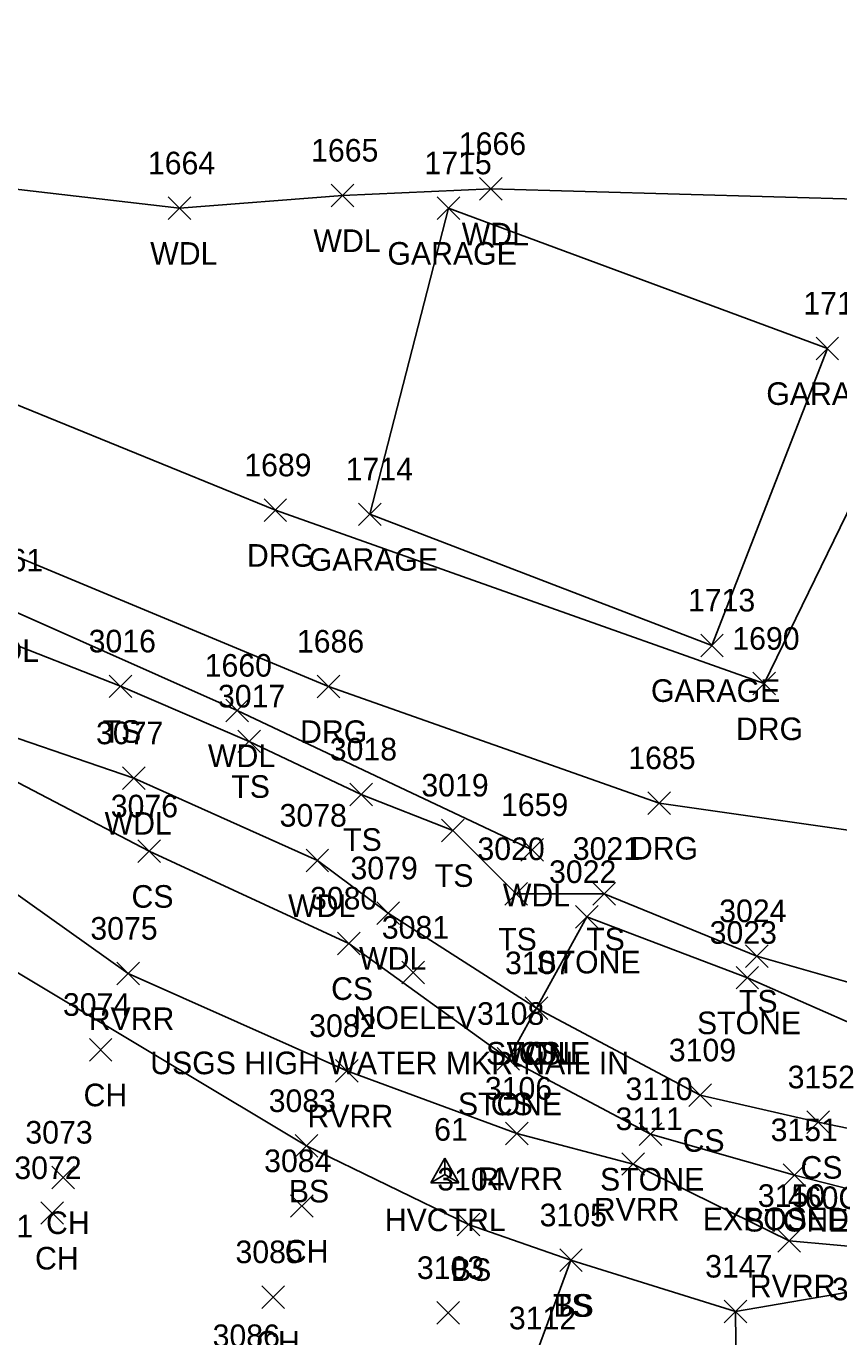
# Model space of a CAD drawing. Extents: x 462930 to 463548, y 29607 to 30453.
# Drawn here: x 463320.55 to 463342.46, y 30140.5 to 30175.85 of the extents above; entities that cross this region are included whole.
import ezdxf

# ---------------------------------------------------------------- set-up
doc = ezdxf.new("R2010")
doc.units = 0
for name, color, linetype in [('C_A', 7, 'Continuous'), ('C_I', 7, 'Continuous'), ('CPSM', 7, 'Continuous'), ('D_C', 7, 'Continuous'), ('L_A', 7, 'Continuous'), ('L_I', 7, 'Continuous'), ('L_TIC', 7, 'Continuous'), ('LASF', 7, 'Continuous'), ('LAWA', 7, 'Continuous'), ('LAWE', 7, 'Continuous'), ('LBC', 7, 'Continuous'), ('LELB', 7, 'Continuous'), ('M_A', 7, 'Continuous'), ('M_C', 7, 'Continuous'), ('M_I', 7, 'Continuous'), ('M_TIC', 7, 'Continuous'), ('R_A', 7, 'Continuous'), ('R_I', 7, 'Continuous'), ('R_TIC', 7, 'Continuous'), ('RDG', 7, 'Continuous'), ('U_C', 7, 'Continuous')]:
    doc.layers.add(name, color=color, linetype=linetype)

msp = doc.modelspace()

# ---------------------------------------------------------------- linework, layer by layer
at = {"layer": 'CPSM'}
for p, q in [((463331.458, 30144.654), (463331.839, 30145.314)), ((463332.22, 30144.654), (463331.839, 30145.314)), ((463331.839, 30144.874), (463331.839, 30145.314)), ((463331.458, 30144.654), (463331.839, 30144.874)), ((463331.458, 30144.654), (463332.22, 30144.654)), ((463331.839, 30144.874), (463331.839, 30144.874)), ((463331.839, 30144.874), (463332.22, 30144.654))]:
    msp.add_line(p, q, dxfattribs=at)
at = {"layer": 'L_TIC'}
for points in [[(463328.779, 30170.977), (463329.389, 30171.587)], [(463329.389, 30170.977), (463328.779, 30171.587)], [(463332.778, 30171.156), (463333.388, 30171.766)], [(463333.388, 30171.156), (463332.778, 30171.766)], [(463324.379, 30170.634), (463324.989, 30171.244)], [(463324.989, 30170.634), (463324.379, 30171.244)], [(463331.633, 30170.635), (463332.243, 30171.245)], [(463332.243, 30170.635), (463331.633, 30171.245)], [(463341.846, 30166.853), (463342.456, 30167.463)], [(463342.456, 30166.853), (463341.846, 30167.463)], [(463329.51, 30162.378), (463330.12, 30162.988)], [(463330.12, 30162.378), (463329.51, 30162.988)], [(463338.736, 30158.843), (463339.346, 30159.453)], [(463339.346, 30158.843), (463338.736, 30159.453)], [(463322.793, 30157.74), (463323.403, 30158.349)], [(463323.403, 30157.74), (463322.793, 30158.349)], [(463325.936, 30157.086), (463326.546, 30157.696)], [(463326.546, 30157.086), (463325.936, 30157.696)], [(463326.263, 30156.255), (463326.872, 30156.865)], [(463326.872, 30156.255), (463326.263, 30156.865)], [(463323.15, 30155.262), (463323.76, 30155.872)], [(463323.76, 30155.262), (463323.15, 30155.872)], [(463329.277, 30154.825), (463329.887, 30155.435)], [(463329.887, 30154.825), (463329.277, 30155.435)], [(463331.749, 30153.854), (463332.359, 30154.464)], [(463332.359, 30153.854), (463331.749, 30154.464)], [(463323.563, 30153.291), (463324.172, 30153.901)], [(463324.172, 30153.291), (463323.563, 30153.901)], [(463333.886, 30153.327), (463334.496, 30153.937)], [(463334.496, 30153.327), (463333.886, 30153.937)], [(463328.097, 30153.041), (463328.706, 30153.65)], [(463328.706, 30153.041), (463328.097, 30153.65)], [(463333.457, 30152.139), (463334.066, 30152.749)], [(463334.066, 30152.139), (463333.457, 30152.749)], [(463335.829, 30152.142), (463336.438, 30152.752)], [(463336.438, 30152.142), (463335.829, 30152.752)], [(463330.01, 30151.619), (463330.62, 30152.228)], [(463330.62, 30151.619), (463330.01, 30152.228)], [(463335.361, 30151.52), (463335.971, 30152.129)], [(463335.971, 30151.52), (463335.361, 30152.129)], [(463335.361, 30151.52), (463335.971, 30152.129)], [(463335.971, 30151.52), (463335.361, 30152.129)], [(463328.944, 30150.805), (463329.554, 30151.414)], [(463329.554, 30150.805), (463328.944, 30151.414)], [(463339.948, 30150.464), (463340.558, 30151.074)], [(463340.558, 30150.464), (463339.948, 30151.074)], [(463322.996, 30149.992), (463323.606, 30150.601)], [(463323.606, 30149.992), (463322.996, 30150.601)], [(463339.689, 30149.881), (463340.299, 30150.491)], [(463340.299, 30149.881), (463339.689, 30150.491)], [(463334.002, 30149.061), (463334.612, 30149.67)], [(463334.612, 30149.061), (463334.002, 30149.67)], [(463334.002, 30149.061), (463334.612, 30149.67)], [(463334.612, 30149.061), (463334.002, 30149.67)], [(463334.002, 30149.061), (463334.612, 30149.67)], [(463334.612, 30149.061), (463334.002, 30149.67)], [(463322.256, 30147.938), (463322.866, 30148.547)], [(463322.866, 30147.938), (463322.256, 30148.547)], [(463333.246, 30147.695), (463333.856, 30148.305)], [(463333.856, 30147.695), (463333.246, 30148.305)], [(463333.246, 30147.695), (463333.856, 30148.305)], [(463333.856, 30147.695), (463333.246, 30148.305)], [(463328.895, 30147.368), (463329.505, 30147.977)], [(463329.505, 30147.368), (463328.895, 30147.977)], [(463338.42, 30146.71), (463339.029, 30147.319)], [(463339.029, 30146.71), (463338.42, 30147.319)], [(463338.42, 30146.71), (463339.029, 30147.319)], [(463339.029, 30146.71), (463338.42, 30147.319)], [(463341.597, 30145.983), (463342.207, 30146.593)], [(463342.207, 30145.983), (463341.597, 30146.593)], [(463333.476, 30145.678), (463334.086, 30146.287)], [(463334.086, 30145.678), (463333.476, 30146.287)], [(463337.077, 30145.664), (463337.687, 30146.273)], [(463337.687, 30145.664), (463337.077, 30146.273)], [(463327.803, 30145.343), (463328.413, 30145.952)], [(463328.413, 30145.343), (463327.803, 30145.952)], [(463336.612, 30144.856), (463337.222, 30145.465)], [(463337.222, 30144.856), (463336.612, 30145.465)], [(463321.244, 30144.492), (463321.854, 30145.101)], [(463321.854, 30144.492), (463321.244, 30145.101)], [(463340.964, 30144.558), (463341.574, 30145.168)], [(463341.574, 30144.558), (463340.964, 30145.168)], [(463327.681, 30143.723), (463328.291, 30144.333)], [(463328.291, 30143.723), (463327.681, 30144.333)], [(463320.947, 30143.535), (463321.557, 30144.144)], [(463321.557, 30143.535), (463320.947, 30144.144)], [(463332.176, 30143.227), (463332.785, 30143.837)], [(463332.785, 30143.227), (463332.176, 30143.837)], [(463340.819, 30142.784), (463341.429, 30143.394)], [(463341.429, 30142.784), (463340.819, 30143.394)], [(463334.935, 30142.261), (463335.545, 30142.87)], [(463335.545, 30142.261), (463334.935, 30142.87)], [(463334.935, 30142.261), (463335.545, 30142.87)], [(463335.545, 30142.261), (463334.935, 30142.87)], [(463326.908, 30141.267), (463327.518, 30141.876)], [(463327.518, 30141.267), (463326.908, 30141.876)], [(463331.625, 30140.84), (463332.235, 30141.449)], [(463332.235, 30140.84), (463331.625, 30141.449)], [(463339.373, 30140.878), (463339.983, 30141.488)], [(463339.983, 30140.878), (463339.373, 30141.488)], [(463339.373, 30140.878), (463339.983, 30141.488)], [(463339.983, 30140.878), (463339.373, 30141.488)]]:
    msp.add_lwpolyline(points, dxfattribs=at)
at = {"layer": 'LASF'}
for points in [[(463335.666, 30151.825), (463334.307, 30149.365), (463333.551, 30148), (463337.382, 30145.968), (463341.269, 30144.863), (463346.266, 30143.58), (463350.176, 30142.23), (463354.589, 30140.054), (463359.587, 30137.022), (463360.802, 30137.163)], [(463335.666, 30151.825), (463339.994, 30150.186), (463344.731, 30148.092), (463345.991, 30147.14), (463346.905, 30145.251), (463349.408, 30144.305), (463351.788, 30143.206), (463354.335, 30142.295), (463356.35, 30141.031), (463357.426, 30140.903), (463358.46, 30140.002), (463361.001, 30139.273), (463362.41, 30138.437), (463365.572, 30136.833), (463366.432, 30136.349), (463367.765, 30135.728), (463368.18, 30135.769), (463368.592, 30135.381), (463370.057, 30136.689), (463370.978, 30134.911), (463374.408, 30132.631)]]:
    msp.add_lwpolyline(points, dxfattribs=at)
at = {"layer": 'LAWA'}
for points in [[(463334.191, 30153.632), (463326.241, 30157.391), (463319.877, 30160.227), (463314.478, 30162.732), (463317.175, 30171.812), (463324.684, 30170.939), (463329.084, 30171.282), (463333.083, 30171.461), (463343.25, 30171.173), (463352.596, 30169.581), (463356.899, 30175.447), (463361.663, 30184.45), (463356.272, 30186.994), (463347.611, 30186.575), (463333.194, 30190.781), (463330.167, 30185.817), (463328.348, 30182.689), (463321.007, 30182.589)], [(463314.174, 30158.759), (463318.783, 30157.171), (463323.455, 30155.567), (463328.402, 30153.346), (463330.315, 30151.924), (463334.307, 30149.365)]]:
    msp.add_lwpolyline(points, dxfattribs=at)
at = {"layer": 'LAWE'}
msp.add_lwpolyline([(463312.771, 30156.48), (463317.927, 30154.119), (463323.301, 30150.297), (463329.2, 30147.672), (463333.781, 30145.982), (463336.917, 30145.16), (463341.124, 30143.089), (463345.902, 30142.661), (463349.953, 30140.952), (463354.589, 30140.054), (463360.802, 30137.163), (463361.685, 30137.202), (463364.938, 30136.029), (463367.213, 30134.485), (463367.529, 30133.847), (463370.878, 30131.969), (463372.536, 30131.581), (463374.072, 30131.794), (463376.13, 30130.821), (463379.432, 30129.045)], dxfattribs=at)
at = {"layer": 'LBC'}
for points in [[(463342.151, 30167.158), (463339.041, 30159.148), (463329.815, 30162.683), (463331.938, 30170.94)], [(463331.938, 30170.94), (463342.151, 30167.158)]]:
    msp.add_lwpolyline(points, dxfattribs=at)
at = {"layer": 'LELB'}
for points in [[(463315.632, 30161.314), (463319.611, 30159.411), (463323.098, 30158.045), (463326.567, 30156.56), (463329.582, 30155.13), (463332.054, 30154.159), (463333.762, 30152.444), (463336.134, 30152.447), (463340.253, 30150.769), (463345.161, 30149.365), (463346.778, 30148.746), (463346.708, 30147.71), (463349.033, 30147.393), (463350.898, 30147.395), (463351.713, 30147.754), (463353.797, 30146.756), (463354.253, 30145.629), (463355.291, 30145.255), (463356.709, 30145.503), (463357.92, 30145.112), (463358.601, 30144.516), (463359.186, 30143.714)], [(463313.769, 30158.17), (463318.774, 30156.259), (463323.868, 30153.596), (463329.249, 30151.11), (463333.551, 30148)], [(463311.51, 30154.564), (463317.305, 30152.12), (463328.108, 30145.648), (463332.48, 30143.532), (463335.24, 30142.565), (463339.678, 30141.183), (463343.544, 30141.846), (463345.752, 30141.37), (463349.534, 30139.719), (463354.026, 30138.661), (463359.587, 30137.022), (463361.306, 30136.712), (463364.334, 30135.56), (463366.649, 30133.733), (463367.281, 30133.213), (463370.369, 30131.577), (463372.89, 30130.394), (463376, 30129.47), (463379.084, 30127.97)], [(463334.307, 30149.365), (463338.725, 30147.014)], [(463338.725, 30147.014), (463341.902, 30146.288), (463346.905, 30145.251), (463349.39, 30146.891), (463350.92, 30147.048), (463352.297, 30147.355), (463353.139, 30145.924), (463354.358, 30144.307), (463355.85, 30144.681), (463357.539, 30144.184), (463357.985, 30144.223), (463357.945, 30143.102), (463357.652, 30141.391), (463358.461, 30140.69), (463361.001, 30139.273)], [(463335.24, 30142.565), (463334.214, 30139.787), (463334.684, 30135.891)], [(463338.428, 30135.653), (463339.702, 30138.688), (463339.678, 30141.183)]]:
    msp.add_lwpolyline(points, dxfattribs=at)
at = {"layer": 'M_TIC'}
for points in [[(463330.68, 30150.02), (463331.289, 30150.63)], [(463331.289, 30150.02), (463330.68, 30150.63)]]:
    msp.add_lwpolyline(points, dxfattribs=at)
at = {"layer": 'R_TIC'}
for points in [[(463326.965, 30162.489), (463327.575, 30163.099)], [(463327.575, 30162.489), (463326.965, 30163.099)], [(463340.146, 30157.812), (463340.756, 30158.422)], [(463340.756, 30157.812), (463340.146, 30158.422)], [(463328.398, 30157.735), (463329.008, 30158.345)], [(463329.008, 30157.735), (463328.398, 30158.345)], [(463337.315, 30154.591), (463337.925, 30155.201)], [(463337.925, 30154.591), (463337.315, 30155.201)]]:
    msp.add_lwpolyline(points, dxfattribs=at)
at = {"layer": 'RDG'}
msp.add_lwpolyline([(463347.931, 30153.415), (463337.62, 30154.896), (463328.703, 30158.04), (463317.438, 30162.728), (463318.8, 30166.246), (463327.27, 30162.794), (463340.451, 30158.117), (463344.729, 30166.901), (463353.138, 30164.992), (463357.576, 30167.469)], dxfattribs=at)

# ---------------------------------------------------------------- texts
at = {"layer": 'C_A'}
msp.add_text('HVCTRL', height=0.6096, dxfattribs=at).set_placement((463330.221, 30143.35))
at = {"layer": 'C_I'}
msp.add_text('61', height=0.6096, dxfattribs=at).set_placement((463331.551, 30145.789))
at = {"layer": 'D_C'}
msp.add_text('460CGMP', height=0.6096, dxfattribs=at).set_placement((463341.089, 30143.947))
at = {"layer": 'L_A'}
for s, p in [('WDL', (463332.296, 30169.937)), ('WDL', (463323.897, 30169.415)), ('WDL', (463328.297, 30169.758)), ('GARAGE', (463330.292, 30169.416)), ('GARAGE', (463340.505, 30165.634)), ('GARAGE', (463328.169, 30161.159)), ('WDL', (463319.09, 30158.703)), ('GARAGE', (463337.395, 30157.624)), ('TS', (463322.613, 30156.521)), ('WDL', (463325.454, 30155.867)), ('TS', (463326.083, 30155.036)), ('WDL', (463322.668, 30154.043)), ('TS', (463329.097, 30153.606)), ('TS', (463331.569, 30152.635)), ('WDL', (463333.404, 30152.108)), ('CS', (463323.392, 30152.072)), ('WDL', (463327.614, 30151.822)), ('TS', (463333.277, 30150.92)), ('TS', (463335.649, 30150.923)), ('WDL', (463329.528, 30150.4)), ('STONE', (463334.308, 30150.301)), ('STONE', (463334.308, 30150.301)), ('CS', (463328.774, 30149.586)), ('TS', (463339.768, 30149.245)), ('RVRR', (463322.238, 30148.773)), ('STONE', (463338.636, 30148.662)), ('STONE', (463332.949, 30147.841)), ('CS', (463333.832, 30147.841)), ('WDL', (463333.52, 30147.841)), ('CH', (463322.1, 30146.718)), ('STONE', (463332.193, 30146.476)), ('CS', (463333.076, 30146.476)), ('RVRR', (463328.137, 30146.148)), ('CS', (463338.249, 30145.49)), ('CS', (463338.249, 30145.49)), ('CS', (463341.427, 30144.764)), ('RVRR', (463332.718, 30144.458)), ('STONE', (463336.024, 30144.444)), ('BS', (463327.633, 30144.124)), ('RVRR', (463335.854, 30143.636)), ('CH', (463321.088, 30143.272)), ('STONE', (463339.91, 30143.339)), ('CH', (463320.791, 30142.315)), ('CH', (463327.525, 30142.504)), ('BS', (463332.005, 30142.008)), ('RVRR', (463340.061, 30141.565)), ('TS', (463334.755, 30141.041)), ('BS', (463334.765, 30141.041)), ('CH', (463326.752, 30140.047))]:
    msp.add_text(s, height=0.6096, dxfattribs=at).set_placement(p)
at = {"layer": 'L_I'}
for s, p in [('1666', (463332.217, 30172.375)), ('1665', (463328.234, 30172.196)), ('1664', (463323.834, 30171.853)), ('1715', (463331.29, 30171.854)), ('1712', (463341.503, 30168.072)), ('1714', (463329.167, 30163.597)), ('1661', (463319.2, 30161.141)), ('1713', (463338.393, 30160.062)), ('3016', (463322.237, 30158.959)), ('1660', (463325.365, 30158.305)), ('3017', (463325.723, 30157.475)), ('3077', (463322.437, 30156.482)), ('3018', (463328.737, 30156.045)), ('3019', (463331.207, 30155.073)), ('3076', (463322.833, 30154.51)), ('3078', (463327.384, 30154.26)), ('1659', (463333.353, 30154.546)), ('3020', (463332.718, 30153.358)), ('3021', (463335.289, 30153.362)), ('3079', (463329.295, 30152.838)), ('3022', (463334.649, 30152.739)), ('3022', (463334.649, 30152.739)), ('3080', (463328.205, 30152.024)), ('3024', (463339.236, 30151.684)), ('3075', (463322.283, 30151.211)), ('3023', (463338.977, 30151.1)), ('3107', (463333.462, 30150.28)), ('3107', (463333.462, 30150.28)), ('3107', (463333.462, 30150.28)), ('3074', (463321.544, 30149.157)), ('3108', (463332.706, 30148.914)), ('3108', (463332.706, 30148.914)), ('3082', (463328.182, 30148.587)), ('3109', (463337.878, 30147.929)), ('3109', (463337.878, 30147.929)), ('3152', (463341.081, 30147.202)), ('3106', (463332.919, 30146.897)), ('3110', (463336.708, 30146.883)), ('3083', (463327.091, 30146.562)), ('3111', (463336.442, 30146.075)), ('3151', (463340.621, 30145.778)), ('3073', (463320.531, 30145.711)), ('3072', (463320.235, 30144.754)), ('3084', (463326.968, 30144.942)), ('3104', (463331.636, 30144.447)), ('3150', (463340.277, 30144.004)), ('3105', (463334.395, 30143.48)), ('3105', (463334.395, 30143.48)), ('3071', (463318.931, 30143.181)), ('3085', (463326.195, 30142.486)), ('3103', (463331.086, 30142.059)), ('3147', (463338.857, 30142.098)), ('3147', (463338.857, 30142.098)), ('3149', (463342.271, 30141.484)), ('3112', (463333.566, 30140.702)), ('3086', (463325.579, 30140.223))]:
    msp.add_text(s, height=0.6096, dxfattribs=at).set_placement(p)
at = {"layer": 'M_A'}
msp.add_text('NOELEV', height=0.6096, dxfattribs=at).set_placement((463329.379, 30148.801))
at = {"layer": 'M_C'}
msp.add_text('USGS HIGH WATER MKR-NAIL IN', height=0.6096, dxfattribs=at).set_placement((463323.897, 30147.582))
at = {"layer": 'M_I'}
msp.add_text('3081', height=0.6096, dxfattribs=at).set_placement((463330.14, 30151.239))
at = {"layer": 'R_A'}
for p in [(463326.504, 30161.27), (463327.937, 30156.516), (463339.685, 30156.593), (463336.854, 30153.372)]:
    msp.add_text('DRG', height=0.6096, dxfattribs=at).set_placement(p)
at = {"layer": 'R_I'}
for s, p in [('1689', (463326.432, 30163.708)), ('1686', (463327.851, 30158.954)), ('1690', (463339.589, 30159.031)), ('1685', (463336.785, 30155.81))]:
    msp.add_text(s, height=0.6096, dxfattribs=at).set_placement(p)
at = {"layer": 'U_C'}
msp.add_text('EXPOSED ATTACHED TO BRIDGE', height=0.6096, dxfattribs=at).set_placement((463338.792, 30143.375))

doc.saveas('drawing.dxf')
